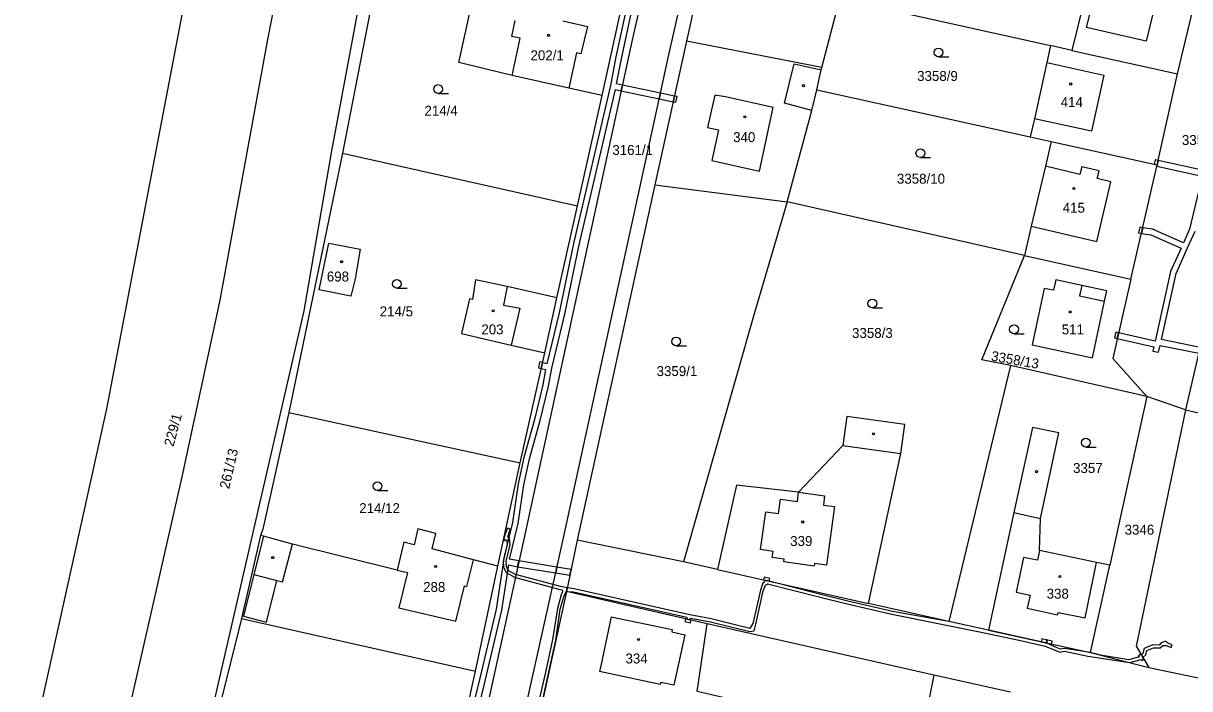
# Model space of a CAD drawing. Extents: x -776734 to -748832, y -1118122 to -976986.
# Drawn here: x -752841.8 to -752642.5, y -1114549.6 to -1114435.8 of the extents above; entities that cross this region are included whole.
import ezdxf

# ---------------------------------------------------------------- set-up
doc = ezdxf.new("R2010")
doc.units = 0
for name, color, linetype in [('KM_Hranice parcel', 7, 'Continuous'), ('KM_Parcelní čísla', 7, 'Continuous'), ('KM_Vnitřní kresba', 7, 'Continuous'), ('KM_Věcná břemena k části', 7, 'Continuous'), ('KM_Značky budov', 7, 'Continuous'), ('KM_Značky kultur', 7, 'Continuous')]:
    doc.layers.add(name, color=color, linetype=linetype)

msp = doc.modelspace()

# ---------------------------------------------------------------- linework, layer by layer
at = {"layer": 'KM_Hranice parcel'}
for p, q in [((-752724.68, -1114380.43), (-752737.81, -1114438.9)), ((-752731.48, -1114441.22), (-752718.25, -1114381.79)), ((-752778.64, -1114413.38), (-752787.24, -1114458.01)), ((-752722.9, -1114414.01), (-752728.48, -1114438.87)), ((-752644.51, -1114444.45), (-752640.79, -1114428.85)), ((-752742.9, -1114448.15), (-752739.45, -1114432.61)), ((-752705.34, -1114443.39), (-752702.24, -1114431.56)), ((-752702.24, -1114431.56), (-752666.25, -1114439.62)), ((-752728.48, -1114438.87), (-752733.86, -1114463.42)), ((-752705.34, -1114443.39), (-752728.48, -1114438.87)), ((-752662.61, -1114440.44), (-752666.25, -1114439.62)), ((-752662.61, -1114440.44), (-752644.51, -1114444.45)), ((-752648.02, -1114460.02), (-752644.51, -1114444.45)), ((-752747.08, -1114467), (-752742.9, -1114448.15)), ((-752706.2, -1114447.2), (-752669.69, -1114455.24)), ((-752669.69, -1114455.24), (-752666.11, -1114456.03)), ((-752666.11, -1114456.03), (-752648.02, -1114460.02)), ((-752787.24, -1114458.01), (-752796.46, -1114502.32)), ((-752787.24, -1114458.01), (-752747.08, -1114467)), ((-752652.49, -1114479.57), (-752648.02, -1114460.02)), ((-752733.86, -1114463.42), (-752747.13, -1114524.16)), ((-752733.86, -1114463.42), (-752711.24, -1114466.35)), ((-752670.71, -1114475.52), (-752711.24, -1114466.35)), ((-752750.6, -1114482.76), (-752747.08, -1114467)), ((-752670.71, -1114475.52), (-752652.49, -1114479.57)), ((-752752.7, -1114492.13), (-752750.6, -1114482.76)), ((-752638.65, -1114482.47), (-752643.14, -1114501.91)), ((-752756.9, -1114510.93), (-752752.7, -1114492.13)), ((-752673.07, -1114494.31), (-752683.64, -1114538.08)), ((-752649.75, -1114499.63), (-752673.07, -1114494.31)), ((-752649.75, -1114499.63), (-752656.09, -1114528.46)), ((-752643.14, -1114501.91), (-752649.75, -1114499.63)), ((-752796.46, -1114502.32), (-752756.9, -1114510.93)), ((-752643.14, -1114501.91), (-752627.01, -1114505.53)), ((-752760.69, -1114528.61), (-752756.9, -1114510.93)), ((-752801.28, -1114523.36), (-752804.54, -1114537.58)), ((-752747.13, -1114524.16), (-752749, -1114532.92)), ((-752729, -1114527.9), (-752747.13, -1114524.16)), ((-752764.54, -1114546.58), (-752760.69, -1114528.61)), ((-752723.14, -1114529.21), (-752729, -1114527.9)), ((-752659.38, -1114543.4), (-752656.09, -1114528.46)), ((-752723.14, -1114529.21), (-752697.34, -1114535)), ((-752749, -1114532.92), (-752754.22, -1114556.89)), ((-752724.94, -1114538.45), (-752749, -1114532.92)), ((-752683.64, -1114538.08), (-752697.34, -1114535)), ((-752804.54, -1114537.58), (-752809.92, -1114559.25)), ((-752804.54, -1114537.58), (-752764.54, -1114546.58)), ((-752686.16, -1114547.25), (-752724.94, -1114538.45)), ((-752676.82, -1114539.57), (-752683.64, -1114538.08)), ((-752676.82, -1114539.57), (-752659.38, -1114543.4)), ((-752659.38, -1114543.4), (-752649.44, -1114545.92)), ((-752770.68, -1114573.97), (-752764.54, -1114546.58)), ((-752649.44, -1114545.92), (-752610.12, -1114554.29)), ((-752686.16, -1114547.25), (-752691.12, -1114570.95)), ((-752673.07, -1114550.14), (-752686.16, -1114547.25))]:
    msp.add_line(p, q, dxfattribs=at)
for points in [[(-752877.51, -1114796.45), (-752864.37, -1114734.66), (-752855.23, -1114695.41), (-752848.48, -1114668.5), (-752842.28, -1114639.9), (-752832.25, -1114590.62), (-752814.67, -1114513.35), (-752808.19, -1114483.16), (-752800.05, -1114438.6), (-752784.13, -1114357.8), (-752769.94, -1114301.29), (-752757.23, -1114242.84)], [(-752784.53, -1114297.81), (-752790.74, -1114319.93), (-752803.68, -1114380.05), (-752814.75, -1114434.38), (-752827.59, -1114501.73), (-752840.34, -1114559.14), (-752851.92, -1114616.56), (-752864.77, -1114671.34), (-752878.1, -1114727), (-752891.1, -1114788.07)], [(-752841.41, -1114701.06), (-752813.72, -1114571.41), (-752793.81, -1114484.96), (-752789.11, -1114457.63), (-752769.97, -1114355.06), (-752767.59, -1114346.94)], [(-752658.74, -1114424.85), (-752659.18, -1114426.61), (-752660.37, -1114431.4), (-752662.61, -1114440.44)], [(-752742.9, -1114448.15), (-752748.56, -1114446.89), (-752758.29, -1114444.73), (-752767.38, -1114442.51), (-752764.26, -1114428.28)], [(-752737.81, -1114438.9), (-752756.29, -1114523.99), (-752769.16, -1114582.75)], [(-752666.25, -1114439.62), (-752666.89, -1114442.52), (-752669, -1114452.12), (-752669.69, -1114455.24)], [(-752763.38, -1114586.25), (-752749.37, -1114523.24), (-752731.48, -1114441.22)], [(-752706.2, -1114447.2), (-752705.43, -1114443.78), (-752705.34, -1114443.39)], [(-752711.24, -1114466.35), (-752707.03, -1114450.7), (-752706.2, -1114447.2)], [(-752666.11, -1114456.03), (-752667.11, -1114460.26), (-752669.52, -1114470.48), (-752670.71, -1114475.52)], [(-752711.24, -1114466.35), (-752716.89, -1114485.48), (-752729, -1114527.9)], [(-752791.23, -1114481.38), (-752789.63, -1114473.41), (-752784.26, -1114474.43), (-752785.11, -1114479.51), (-752785.86, -1114482.46), (-752791.23, -1114481.38)], [(-752673.07, -1114494.31), (-752677.97, -1114493.32), (-752670.71, -1114475.52)], [(-752750.6, -1114482.76), (-752759.11, -1114480.8), (-752764.51, -1114479.67), (-752765.07, -1114483.03), (-752765.56, -1114482.94), (-752766.92, -1114488.86), (-752758.45, -1114490.81), (-752752.7, -1114492.13)], [(-752665.74, -1114481.46), (-752667.31, -1114481.13), (-752669.35, -1114490.79), (-752659.04, -1114493), (-752657, -1114483.31), (-752656.6, -1114481.52), (-752660.88, -1114480.61), (-752665.32, -1114479.66), (-752665.74, -1114481.46)], [(-752652.49, -1114479.57), (-752655.6, -1114493.13), (-752649.75, -1114499.63)], [(-752796.46, -1114502.32), (-752800.87, -1114522.27), (-752801.28, -1114523.36)], [(-752643.14, -1114501.91), (-752651.59, -1114542.32), (-752649.44, -1114545.92)], [(-752697.34, -1114535), (-752691.83, -1114509.34), (-752691.14, -1114504.38), (-752701.06, -1114503.02), (-752701.74, -1114507.97), (-752709.29, -1114515.98), (-752719.91, -1114514.75), (-752723.14, -1114529.21)], [(-752656.09, -1114528.46), (-752658.37, -1114527.99), (-752668.12, -1114525.96), (-752667.96, -1114520.48), (-752664.84, -1114505.85), (-752669.34, -1114504.89), (-752672.51, -1114519.44), (-752676.82, -1114539.57)], [(-752760.69, -1114528.61), (-752764.9, -1114527.51), (-752771.96, -1114525.67), (-752771.31, -1114523.01), (-752774.39, -1114522.26), (-752775.04, -1114524.96), (-752776.79, -1114524.54), (-752777.93, -1114529.28), (-752795.79, -1114524.83), (-752800.75, -1114523.5), (-752801.28, -1114523.36)], [(-752721.53, -1114564.17), (-752721.47, -1114563.92), (-752720.09, -1114558.05), (-752718.77, -1114551.85), (-752726.64, -1114550.07), (-752724.94, -1114538.45)]]:
    msp.add_lwpolyline(points, dxfattribs=at)
at = {"layer": 'KM_Vnitřní kresba'}
for p, q in [((-752647.56, -1114429.41), (-752649.86, -1114438.88)), ((-752660.06, -1114436.54), (-752658.89, -1114431.76)), ((-752758.33, -1114438.04), (-752757.73, -1114435.31)), ((-752749.6, -1114435.39), (-752745.41, -1114436.34)), ((-752745.41, -1114436.34), (-752746.5, -1114441.04)), ((-752649.86, -1114438.88), (-752660.06, -1114436.54)), ((-752756.87, -1114438.37), (-752758.33, -1114438.04)), ((-752758.29, -1114444.73), (-752756.87, -1114438.37)), ((-752747.27, -1114440.86), (-752748.56, -1114446.89)), ((-752746.5, -1114441.04), (-752747.27, -1114440.86)), ((-752711.7, -1114449.47), (-752710.06, -1114442.76)), ((-752710.06, -1114442.76), (-752705.43, -1114443.78)), ((-752666.89, -1114442.52), (-752657.1, -1114444.67)), ((-752657.1, -1114444.67), (-752659.22, -1114454.27)), ((-752723.6, -1114448.12), (-752724.86, -1114453.62)), ((-752721.79, -1114448.4), (-752723.6, -1114448.12)), ((-752713.63, -1114450.18), (-752721.79, -1114448.4)), ((-752716, -1114461.07), (-752713.63, -1114450.18)), ((-752707.03, -1114450.7), (-752711.7, -1114449.47)), ((-752659.22, -1114454.27), (-752669, -1114452.12)), ((-752724.86, -1114453.62), (-752723, -1114454.02)), ((-752723, -1114454.02), (-752724.14, -1114459.28)), ((-752724.14, -1114459.28), (-752716, -1114461.07)), ((-752661.21, -1114461.66), (-752667.11, -1114460.26)), ((-752660.9, -1114460.33), (-752661.21, -1114461.66)), ((-752657.94, -1114461.04), (-752660.9, -1114460.33)), ((-752658.3, -1114473.13), (-752655.92, -1114462.9)), ((-752658.25, -1114462.36), (-752657.94, -1114461.04)), ((-752655.92, -1114462.9), (-752658.25, -1114462.36)), ((-752669.52, -1114470.48), (-752658.3, -1114473.13)), ((-752759.11, -1114480.8), (-752759.76, -1114484.01)), ((-752660.88, -1114480.61), (-752661.26, -1114482.41)), ((-752661.26, -1114482.41), (-752657, -1114483.31)), ((-752759.76, -1114484.01), (-752756.96, -1114484.53)), ((-752756.96, -1114484.53), (-752758.45, -1114490.81)), ((-752701.74, -1114507.97), (-752691.83, -1114509.34)), ((-752709.5, -1114517.56), (-752709.29, -1114515.98)), ((-752709.29, -1114515.98), (-752704.85, -1114516.58)), ((-752704.85, -1114516.58), (-752705.06, -1114518.16)), ((-752712.72, -1114519.62), (-752712.37, -1114517.17)), ((-752712.37, -1114517.17), (-752709.5, -1114517.56)), ((-752705.06, -1114518.16), (-752703.19, -1114518.41)), ((-752703.19, -1114518.41), (-752704.54, -1114528.43)), ((-752715.84, -1114525.78), (-752714.88, -1114519.3)), ((-752714.88, -1114519.3), (-752712.72, -1114519.62)), ((-752672.51, -1114519.44), (-752667.96, -1114520.48)), ((-752800.75, -1114523.5), (-752802.4, -1114530.06)), ((-752797.52, -1114531.29), (-752795.79, -1114524.83)), ((-752713.67, -1114526.09), (-752715.84, -1114525.78)), ((-752713.82, -1114527.13), (-752713.67, -1114526.09)), ((-752668.12, -1114525.96), (-752668.47, -1114527.61)), ((-752766.02, -1114532.1), (-752764.9, -1114527.51)), ((-752711.76, -1114527.42), (-752713.82, -1114527.13)), ((-752711.82, -1114527.89), (-752711.76, -1114527.42)), ((-752706.66, -1114528.61), (-752711.82, -1114527.89)), ((-752706.6, -1114528.14), (-752706.66, -1114528.61)), ((-752704.54, -1114528.43), (-752706.6, -1114528.14)), ((-752670.84, -1114527.11), (-752672.12, -1114533.04)), ((-752668.47, -1114527.61), (-752670.84, -1114527.11)), ((-752660.31, -1114537.43), (-752658.37, -1114527.99)), ((-752802.4, -1114530.06), (-752804.21, -1114537.17)), ((-752802.4, -1114530.06), (-752798.48, -1114531.05)), ((-752777.93, -1114529.28), (-752776.18, -1114529.7)), ((-752776.18, -1114529.7), (-752777.63, -1114535.72)), ((-752800.28, -1114538.17), (-752798.48, -1114531.05)), ((-752798.48, -1114531.05), (-752797.52, -1114531.29)), ((-752767.91, -1114538.01), (-752766.43, -1114532)), ((-752766.43, -1114532), (-752766.02, -1114532.1)), ((-752672.12, -1114533.04), (-752669.74, -1114533.55)), ((-752669.74, -1114533.55), (-752670.22, -1114535.81)), ((-752777.63, -1114535.72), (-752767.91, -1114538.01)), ((-752670.22, -1114535.81), (-752665.04, -1114536.96)), ((-752665.04, -1114536.96), (-752664.95, -1114536.56)), ((-752664.95, -1114536.56), (-752660.31, -1114537.43)), ((-752804.21, -1114537.17), (-752800.28, -1114538.17)), ((-752741.35, -1114537.28), (-752743.13, -1114545.67)), ((-752741.35, -1114537.28), (-752730.89, -1114539.47)), ((-752730.89, -1114539.47), (-752730.97, -1114539.86)), ((-752730.97, -1114539.86), (-752728.75, -1114540.35)), ((-752728.75, -1114540.35), (-752730.62, -1114548.98)), ((-752743.13, -1114545.67), (-752743.33, -1114546.61)), ((-752732.94, -1114548.86), (-752743.33, -1114546.61)), ((-752732.86, -1114548.49), (-752732.94, -1114548.86)), ((-752730.62, -1114548.98), (-752732.86, -1114548.49))]:
    msp.add_line(p, q, dxfattribs=at)
at = {"layer": 'KM_Věcná břemena k části'}
for points in [[(-752739.43, -1114446.37), (-752740.41, -1114446.16), (-752739.53, -1114441.61), (-752737, -1114429.87), (-752736.72, -1114428.11), (-752736.88, -1114427.35), (-752736.19, -1114425.92), (-752734.68, -1114419.67), (-752733.28, -1114412.75), (-752731.17, -1114401.14), (-752730.68, -1114399.29), (-752727.5, -1114387.77), (-752725.75, -1114380.67)], [(-752737.98, -1114429.68), (-752740.55, -1114441.55), (-752741.48, -1114446.43), (-752747.76, -1114473.44), (-752750.25, -1114485.32), (-752752.33, -1114494.02), (-752753.08, -1114493.82), (-752753.3, -1114494.8), (-752752.55, -1114495), (-752753.04, -1114497.61), (-752754.42, -1114503.52), (-752756.25, -1114510.04), (-752757.25, -1114514.53), (-752758.19, -1114521.14), (-752759.71, -1114527.18), (-752759.75, -1114527.73), (-752761.01, -1114535.94), (-752764.02, -1114548.76), (-752767.13, -1114561.22)], [(-752766.17, -1114561.53), (-752763.04, -1114548.96), (-752760.03, -1114536.14), (-752758.84, -1114528.39), (-752757.33, -1114528.72), (-752757.11, -1114527.72), (-752758.71, -1114527.4), (-752757.21, -1114521.33), (-752756.27, -1114514.71), (-752755.28, -1114510.27), (-752753.45, -1114503.74), (-752752.07, -1114497.84), (-752751.48, -1114494.76), (-752749.28, -1114485.53), (-752746.79, -1114473.67), (-752740.62, -1114447.13), (-752739.64, -1114447.34), (-752739.43, -1114446.37)], [(-752640.02, -1114460.95), (-752647.85, -1114459.25), (-752648.02, -1114460.02), (-752648.07, -1114460.23), (-752640.29, -1114461.92), (-752642.46, -1114471.02), (-752643.52, -1114473.32), (-752648.83, -1114471.03), (-752650.47, -1114470.75), (-752650.69, -1114471.72), (-752649.11, -1114471.99), (-752643.93, -1114474.23), (-752645.72, -1114478.26), (-752648.34, -1114490.15), (-752654.59, -1114488.73), (-752654.82, -1114489.71), (-752648.58, -1114491.13), (-752648.74, -1114491.84), (-752647.76, -1114492.06), (-752647.49, -1114490.87), (-752640.9, -1114492.21)], [(-752640.67, -1114491.23), (-752647.27, -1114489.89), (-752644.76, -1114478.57), (-752642.82, -1114474.19), (-752641.51, -1114471.34)], [(-752749, -1114532.92), (-752748.87, -1114532.32), (-752749.44, -1114532.22), (-752750, -1114532.1), (-752750.63, -1114531.95), (-752757.7, -1114530.02), (-752758.92, -1114529.35), (-752759.24, -1114528.63), (-752759.31, -1114527.79), (-752758.61, -1114524.96), (-752758.7, -1114523.83), (-752759.03, -1114523.68), (-752758.59, -1114522.27), (-752759.06, -1114522.12), (-752759.54, -1114523.26), (-752759.75, -1114524.24), (-752759.44, -1114524.31), (-752759.39, -1114524.07), (-752759.18, -1114524.17), (-752759.11, -1114524.92), (-752759.81, -1114527.75), (-752759.74, -1114528.75), (-752759.3, -1114529.71), (-752757.88, -1114530.48), (-752750.75, -1114532.43), (-752750.12, -1114532.58), (-752749.72, -1114532.67), (-752749.68, -1114532.98), (-752749.88, -1114533.52), (-752750.54, -1114535.85), (-752751.36, -1114541.15), (-752752.48, -1114546.53), (-752754.8, -1114556.38)], [(-752779.68, -1114668.77), (-752775.12, -1114649.81), (-752774.87, -1114648.78), (-752773.87, -1114644.63), (-752770.07, -1114628.88), (-752768.92, -1114623.58), (-752765.16, -1114606.26), (-752764.94, -1114605.28), (-752764.88, -1114604.98), (-752764.11, -1114601.55), (-752761.04, -1114587.35), (-752760.83, -1114586.38), (-752759.64, -1114580.9), (-752758.58, -1114576.22), (-752755.68, -1114563.38), (-752755.46, -1114562.4), (-752754.22, -1114556.89), (-752750.81, -1114541.24), (-752750.06, -1114535.95), (-752749.4, -1114533.68), (-752749, -1114532.92)]]:
    msp.add_lwpolyline(points, dxfattribs=at)
for points in [[(-752739.43, -1114446.37), (-752739.64, -1114447.34), (-752733.12, -1114448.72), (-752732.9, -1114447.74)], [(-752730.75, -1114449.22), (-752730.53, -1114448.24), (-752732.9, -1114447.74), (-752733.12, -1114448.72)], [(-752730.53, -1114448.24), (-752730.75, -1114449.22), (-752730.26, -1114449.32), (-752730.04, -1114448.34)], [(-752648.02, -1114460.02), (-752647.85, -1114459.25), (-752648.34, -1114459.14), (-752648.51, -1114459.91)], [(-752650.69, -1114471.72), (-752650.47, -1114470.75), (-752650.96, -1114470.64), (-752651.18, -1114471.61)], [(-752654.82, -1114489.71), (-752654.59, -1114488.73), (-752655.08, -1114488.62), (-752655.31, -1114489.6)], [(-752753.3, -1114494.8), (-752753.08, -1114493.82), (-752753.57, -1114493.71), (-752753.79, -1114494.69)], [(-752757.11, -1114527.72), (-752757.33, -1114528.72), (-752750.82, -1114529.78), (-752750.6, -1114528.79)], [(-752748.41, -1114530.17), (-752748.2, -1114529.18), (-752750.6, -1114528.79), (-752750.82, -1114529.78)], [(-752714.33, -1114531.19), (-752714.22, -1114530.7), (-752715.19, -1114530.48), (-752715.3, -1114530.97), (-752715.07, -1114531.02)], [(-752749, -1114532.92), (-752747.77, -1114533.01), (-752728.42, -1114537.36), (-752728.41, -1114537.65), (-752727.89, -1114537.77), (-752727.76, -1114537.51), (-752724.37, -1114538.11), (-752717.64, -1114539.81), (-752716.87, -1114539.68), (-752716.62, -1114538.51), (-752715.33, -1114532.86), (-752714.98, -1114531.86), (-752714.64, -1114531.66), (-752705.64, -1114533.92), (-752701.21, -1114535), (-752693.35, -1114536.82), (-752678.09, -1114539.92), (-752671.38, -1114541.34), (-752667.13, -1114542.32), (-752665.32, -1114543.03), (-752664.66, -1114543.33), (-752663.85, -1114543.17), (-752659.86, -1114543.98), (-752652.67, -1114545.1), (-752650.76, -1114544.55), (-752650.62, -1114544.74), (-752650.29, -1114544.5), (-752650.44, -1114544.24), (-752650.71, -1114543.8), (-752650.8, -1114543.64), (-752651.2, -1114543.92), (-752651.06, -1114544.11), (-752652.86, -1114544.63), (-752657.68, -1114543.83), (-752659.38, -1114543.4), (-752663.85, -1114542.67), (-752664.6, -1114542.81), (-752665.12, -1114542.57), (-752666.85, -1114541.76), (-752667.83, -1114541.54), (-752676.82, -1114539.57), (-752683.64, -1114538.08), (-752693.25, -1114536.34), (-752701.09, -1114534.52), (-752705.52, -1114533.44), (-752714.33, -1114531.19), (-752715.07, -1114531.02), (-752715.11, -1114531.36), (-752715.4, -1114531.52), (-752715.81, -1114532.72), (-752717.1, -1114538.41), (-752717.62, -1114539.29), (-752724.27, -1114537.63), (-752727.92, -1114536.96), (-752747.67, -1114532.51), (-752748.87, -1114532.32)], [(-752728.63, -1114537.6), (-752728.74, -1114538.09), (-752727.76, -1114538.31), (-752727.65, -1114537.83), (-752727.89, -1114537.77), (-752728.41, -1114537.65)], [(-752667.83, -1114541.54), (-752666.85, -1114541.76), (-752666.74, -1114541.27), (-752667.72, -1114541.05)], [(-752667.02, -1114541.72), (-752666.05, -1114541.94), (-752665.94, -1114541.45), (-752666.91, -1114541.23)], [(-752650.44, -1114544.24), (-752649.97, -1114543.8), (-752649.8, -1114543.05), (-752648.63, -1114542.55), (-752647.48, -1114542.6), (-752647.05, -1114542.18), (-752646.42, -1114542.19), (-752645.62, -1114542.54), (-752645.42, -1114542.08), (-752646.16, -1114541.77), (-752646.52, -1114541.46), (-752647.33, -1114541.74), (-752647.68, -1114542.1), (-752648.73, -1114542.05), (-752650.24, -1114542.69), (-752650.43, -1114543.54), (-752650.71, -1114543.8)]]:
    msp.add_lwpolyline(points, close=True, dxfattribs=at)
at = {"layer": 'KM_Značky budov'}
for centre in [(-752752.0368, -1114437.8692), (-752708.4568, -1114446.4692), (-752662.7868, -1114446.1892), (-752718.4868, -1114451.8192), (-752662.2668, -1114464.0392), (-752787.4168, -1114476.5692), (-752761.5068, -1114484.9692), (-752662.8668, -1114485.1592), (-752696.4968, -1114505.9792), (-752668.6168, -1114512.4592), (-752708.5968, -1114521.0692), (-752799.1968, -1114527.1592), (-752771.3468, -1114528.6892), (-752664.6468, -1114530.3992), (-752736.6668, -1114541.1492)]:
    msp.add_circle(centre, 0.175, dxfattribs=at)
at = {"layer": 'KM_Značky kultur'}
for p, q in [((-752685.393, -1114441.54), (-752683.643, -1114441.54)), ((-752770.913, -1114447.8), (-752769.163, -1114447.8)), ((-752688.483, -1114458.78), (-752686.733, -1114458.78)), ((-752777.973, -1114481.09), (-752776.223, -1114481.09)), ((-752696.693, -1114484.47), (-752694.943, -1114484.47)), ((-752672.473, -1114488.88), (-752670.723, -1114488.88)), ((-752730.233, -1114490.94), (-752728.483, -1114490.94)), ((-752660.203, -1114508.25), (-752658.453, -1114508.25)), ((-752781.283, -1114515.68), (-752779.533, -1114515.68))]:
    msp.add_line(p, q, dxfattribs=at)
for centre in [(-752685.3929, -1114440.7898), (-752770.9129, -1114447.0498), (-752688.4829, -1114458.0298), (-752777.9729, -1114480.3398), (-752696.6929, -1114483.7198), (-752672.4729, -1114488.1298), (-752730.2329, -1114490.1898), (-752660.2029, -1114507.4998), (-752781.2829, -1114514.9298)]:
    msp.add_circle(centre, 0.75, dxfattribs=at)

# ---------------------------------------------------------------- texts
at = {"layer": 'KM_Parcelní čísla'}
for s, p in [('202/1', (-752755.128, -1114442.13)), ('3358/9', (-752689.04, -1114445.66)), ('414', (-752664.5, -1114450.13)), ('214/4', (-752773.26, -1114451.6)), ('340', (-752720.49, -1114456.12)), ('3358/12', (-752643.78, -1114456.62)), ('3161/1', (-752741.14, -1114458.32)), ('3358/10', (-752692.49, -1114463.23)), ('415', (-752664.15, -1114468.19)), ('698', (-752789.945, -1114479.95)), ('214/5', (-752780.9, -1114485.91)), ('203', (-752763.53, -1114488.99)), ('3358/3', (-752700.16, -1114489.6)), ('511', (-752664.32, -1114488.99)), ('3359/1', (-752733.57, -1114496.12)), ('3357', (-752662.38, -1114512.69)), ('214/12', (-752784.4, -1114519.55)), ('3346', (-752653.57, -1114523.23)), ('339', (-752710.74, -1114525.17)), ('288', (-752773.48, -1114533.02)), ('338', (-752666.9, -1114534.17)), ('334', (-752738.89, -1114545.25))]:
    msp.add_text(s, height=1.7, dxfattribs=at).set_placement(p)
for s, rotation, p in [('3358/13', 349.999997, (-752676.477, -1114493.467)), ('229/1', 75, (-752816.168, -1114508.279)), ('261/13', 77, (-752806.651, -1114515.521))]:
    msp.add_text(s, height=1.7, rotation=rotation, dxfattribs=at).set_placement(p)

doc.saveas('drawing.dxf')
